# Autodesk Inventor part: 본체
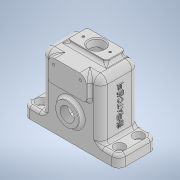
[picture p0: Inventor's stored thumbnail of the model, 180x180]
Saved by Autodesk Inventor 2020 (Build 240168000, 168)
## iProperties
Created: 2023-12
Part Number: 본체
Material: 일반
Document SubType Name: Modeling
Designer: oem
Density: 1 g/cm^3
Appearance: 기본값
Author: oem
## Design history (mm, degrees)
node "3D 스케치1"
sketch "스케치1"
  geometry: L1 (50, -20)-(-50, -20); L2 (-50, -20)-(-50, 20); L3 (-50, 20)-(50, 20); L4 (50, 20)-(50, -20); L5 (50, -20)-(-50, 20); L6 (-50, -20)-(50, 20); 1 further point
  constraints: 12 end point, 2 midpoint, 2 parallel, 1 horizontal, 1 perpendicular
  dimensions: "d0" = 100 distance of L2.end L3.end; "d1" = 40 distance of L1.end L2.end
extrude "돌출1" new body sketch "스케치1" distance "d2" = 12; taper "d3" = 0 deg
sketch "스케치2"
  geometry: L1 (-50, -20)-(50, -20) reference; L2 (50, 20)-(-50, 20) reference; L3 (-31, 20)-(31, 20); L4 (31, 20)-(31, -20); L5 (31, -20)-(-31, -20); L6 (-31, -20)-(-31, 20); L7 (-31, 20)-(31, -20); L8 (31, 20)-(-31, -20); 5 further points
  constraints: 12 end point, 2 midpoint, 2 parallel, 1 horizontal, 1 perpendicular
  dimensions: "d4" = 62 distance of L4.end L5.end; "d5" = 40 distance of L3.end L4.end
extrude "돌출2" join sketch "스케치2" distance "d6" = 60; taper "d7" = 0 deg
sketch "스케치3"
  geometry: L1 (0, 0)-(100, 0) reference; L2 (19, 72)-(81, 72) reference; L3 (30, 72)-(70, 72); L4 (70, 72)-(70, 48); L5 (70, 48)-(30, 48); L6 (30, 48)-(30, 72); 6 further points
  constraints: 8 end point, 4 midpoint, 2 parallel, 1 horizontal, 1 perpendicular, 1 vertical alignment
  dimensions: "d8" = 40 distance of L4.end L5.end; "d9" = 24 distance of L3.end L4.end
extrude "돌출3" join sketch "스케치3" distance "d10" = 4; taper "d11" = 0 deg
sketch "스케치4"
  geometry: L1 (0, 0)-(100, 0) reference; C1 r 12 at (50, 28); 2 further points
  constraints: 1 centre point, 1 midpoint, 1 vertical alignment
  dimensions: "d12" = 24 diameter of C1; "d13" = 28 distance of C1.centre point (50, 0)
extrude "돌출4" join sketch "스케치4" distance "d14" = 4; taper "d15" = 0 deg
sketch "스케치5"
  geometry: L1 (20, -24)-(-20, -24) reference; L2 (-20, 17)-(20, 17); L3 (20, 17)-(20, -3); L4 (20, -3)-(-20, -3); L5 (-20, -3)-(-20, 17); 3 further points
  constraints: 8 end point, 2 midpoint, 2 parallel, 1 horizontal, 1 perpendicular, 1 vertical alignment
  dimensions: "d16" = 40 distance of L3.end L4.end; "d17" = 20 distance of L2.end L3.end; "d18" = 21 distance from line of L3.end L1
extrude "돌출5" join sketch "스케치5" distance "d19" = 4; taper "d20" = 0 deg
sketch "스케치6"
  geometry: L1 (0, 0)-(100, 0) reference; C1 r 20 at (50, 28); 2 further points
  constraints: 1 centre point, 1 midpoint, 1 vertical alignment
  dimensions: "d21" = 40 diameter of C1; "d22" = 28 distance from line of C1.centre L1
extrude "돌출6" join sketch "스케치6" distance "d23" = 4; taper "d24" = 0 deg
sketch "스케치7"
  geometry: L1 (-20, -3)-(20, -3) reference; L2 (20, -3)-(20, 17) reference; L3 (20, 17)-(-20, 17) reference; L4 (-20, 17)-(-20, -3) reference; L5 (-20, -3)-(20, -3) reference; L6 (20, -3)-(20, 17) reference; L7 (20, 17)-(-20, 17) reference; C1 r 8 at (0, 7); 1 further point
  constraints: 1 centre point
  dimensions: "d25" = 16 diameter of C1
extrude "돌출7" cut sketch "스케치7" distance "d26" = 15; taper "d27" = 0 deg
chamfer "모따기1" distance "d28" = 1; stored, may be unused: second distance "d29" = 2, angle "d30" = 45 deg
sketch "스케치9"
  geometry: L1 (-50, 20)-(50, 20) reference; L2 (-50, -20)-(-50, 20); L3 (50, -20)-(-50, -20) reference; L4 (50, 20)-(50, -20); L5 (-50, 20)-(50, 20); L6 (-50, -20)-(-50, 20); L7 (50, -20)-(-50, -20); L8 (50, 20)-(50, -20); L9 (27, 16)-(-27, 16); L10 (-27, 16)-(-27, -16); L11 (-27, -16)-(27, -16); L12 (27, -16)-(27, 16); 4 further points
  constraints: 16 end point, 3 midpoint, 1 horizontal alignment, 1 vertical alignment
  dimensions: "d34" = 4 distance between parallel lines of L1 L9; "d36" = 54 distance of L10.end L11.end; "d37" = 4 distance between parallel lines of L11 L3 (derived)
extrude "돌출9" cut sketch "스케치9" distance "d38" = 68; taper "d39" = 0 deg
sketch "스케치10"
  geometry: L1 (70, 72)-(30, 72) reference; 3 further points
  constraints: 1 horizontal alignment
  dimensions: "d40" = 28 distance of point (64, 66) point (36, 66); "d41" = 6 distance from line of point (36, 66) L1; "d42" = 14 horizontal distance of point (64, 66) point (50, 0)
hole "구멍1" sketch "스케치10" at (36, 66), (64, 66) diameter "d43" = 2.459; stored, may be unused: countersink angle "d47" = 60 deg, drill point angle "d49" = 118 deg; dims "d44" = 15, "d45" = 19.05, "d46" = 4.775, "d48" = 17
sketch "스케치11"
  geometry: L1 (-20, 17)-(-20, -3) reference; L2 (-20, -3)-(20, -3) reference; L3 (20, -3)-(20, 17) reference; L4 (20, 17)-(-20, 17) reference; C1 r 9 at (0, 7) reference; C2 r 9 at (0, 7) reference; 3 further points
  constraints: 2 horizontal alignment
  dimensions: "d50" = 28 distance of point (14, 7) point (-14, 7); "d51" = 14 distance of point (14, 7) C1.centre
hole "구멍2" sketch "스케치11" at (-14, 7), (14, 7) diameter "d52" = 2.459; stored, may be unused: countersink angle "d56" = 60 deg, drill point angle "d58" = 118 deg; dims "d53" = 15, "d54" = 19.05, "d55" = 4.775, "d57" = 17
sketch "스케치12"
  geometry: C1 r 20 at (0, 0) reference; A1 r 15 centre (0, 0) between (0, 15) and (0, -15); 3 further points
  constraints: 4 point on circle, 2 horizontal alignment, 2 vertical alignment, 1 centre point, 1 coincident
  dimensions: "d59" = 30 diameter of A1
hole "구멍3" sketch "스케치12" at (0, 15), (0, -15), (15, 0), (-15, 0) diameter "d60" = 2.459; stored, may be unused: countersink angle "d64" = 60 deg, drill point angle "d66" = 118 deg; dims "d61" = 15, "d62" = 19.05, "d63" = 4.775, "d65" = 17
sketch "스케치15"
  geometry: C1 r 12 at (0, 0) reference; 2 further points
  constraints: 1 coincident
hole "구멍4" sketch "스케치15" at (0, 0) diameter "d71" = 14.91747; stored, may be unused: countersink angle "d75" = 60 deg, drill point angle "d77" = 118 deg; dims "d72" = 15, "d73" = 19.05, "d74" = 4.775, "d76" = 15
sketch "스케치16"
  geometry: C1 r 20 at (0, 0) reference; C2 r 9 at (0, 0); 1 further point
  constraints: 1 centre point, 1 coincident
  dimensions: "d78" = 18 diameter of C2
extrude "돌출11" cut sketch "스케치16" distance "d79" = 20; taper "d80" = 0 deg
fillet "모깎기1" dims "d81" = 7
sketch "스케치18"
  geometry: L1 (-43, -20)-(-31, -20) reference; 3 further points
  constraints: 1 vertical alignment
  dimensions: "d92" = 20 distance of point (-41, -10) point (-41, 10); "d93" = 41 horizontal distance of point (-41, 10) point (0, 0); "d94" = 10 distance from line of point (-41, -10) L1
hole "구멍6" sketch "스케치18" at (-41, 10), (-41, -10) diameter "d95" = 6.6; stored, may be unused: countersink angle "d99" = 60 deg, drill point angle "d101" = 118 deg; dims "d96" = 15, "d97" = 11, "d98" = 6.6, "d100" = 15
fillet "모깎기2" dims "d102" = 7
fillet "모깎기3" dims "d103" = 7
fillet "모깎기4" dims "d104" = 7
fillet "모깎기5" dims "d105" = 3
fillet "모깎기6" dims "d106" = 3
fillet "모깎기7" dims "d107" = 3
fillet "모깎기8" dims "d108" = 3
fillet "모깎기9" dims "d109" = 3
fillet "모깎기10" dims "d110" = 3
fillet "모깎기11" dims "d111" = 3
fillet "모깎기12" dims "d112" = 3
chamfer "모따기2" distance "d113" = 1; stored, may be unused: second distance "d114" = 2, angle "d115" = 45 deg
fillet "모깎기13" dims "d116" = 3
fillet "모깎기14" dims "d117" = 3
node "작업 평면1"
sketch "스케치19"
  geometry: 1 further point
sketch "스케치20"
  geometry: L1 (0, -65)-(26, -65) reference; L2 (-11, -25)-(-11, -49) reference; L3 (26, -50)-(0, -50) reference; L4 (26, 0)-(26, -50) reference; L5 (0, 0)-(26, 0) reference; L6 (0, -50)-(0, 0) reference; 3 further points
  constraints: 1 midpoint, 1 vertical alignment, 1 other
  dimensions: "d119" = 40 distance from line of point (13, -25) L1
feature "엠보싱1" sketch "스케치20" dims "d120" = 1, "d121" = 0
node "솔리드1"
mirror "미러1"
node "투영된 루프1"
node "투영된 루프3"
node "투영된 루프4"
feature "A9D066F2-1C7D-4E18-AEED-F7BC21143FA4" dims "d43" = 2.459, "d44" = 15, "d45" = 19.05, "d46" = 4.775, "d47" = 60 deg, "d48" = 17, "d49" = 118 deg
